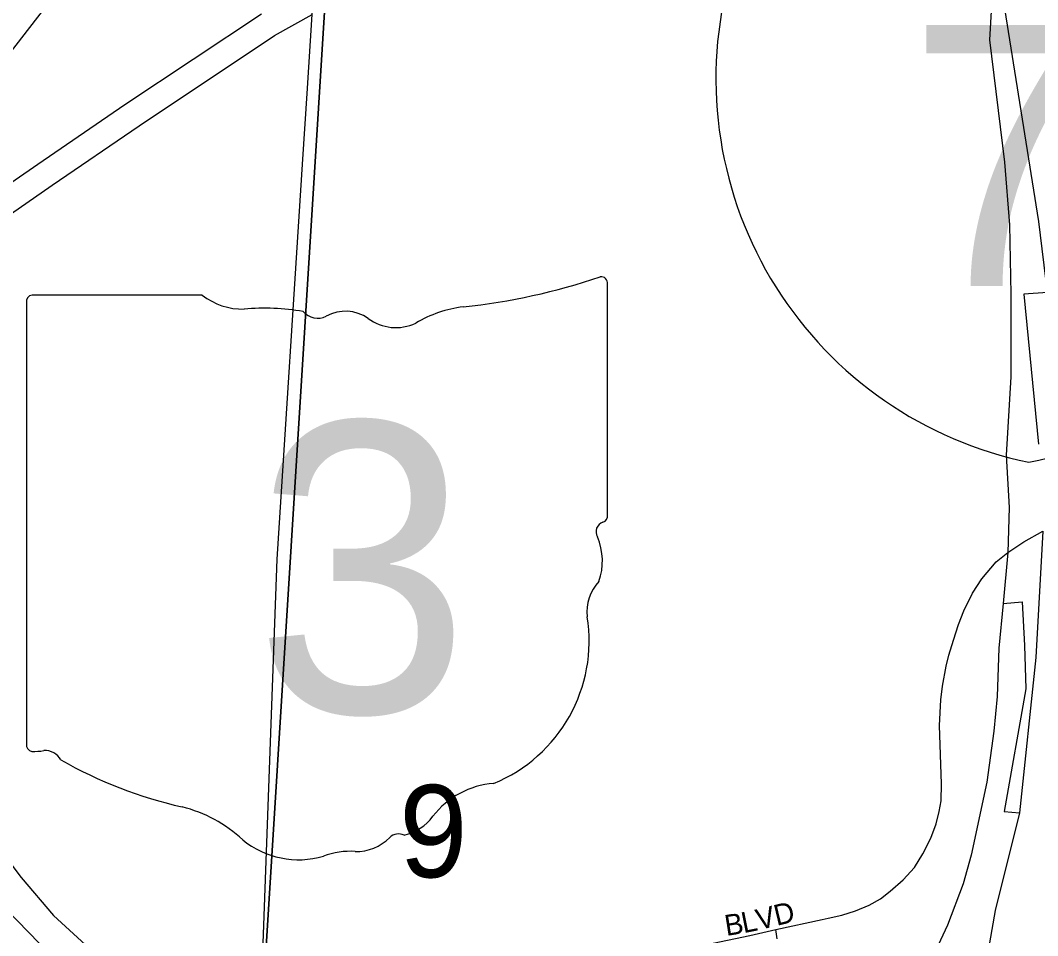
# Model space of a CAD drawing. Extents: x 0 to 34, y -6.2 to 22.
# Drawn here: x 7.114 to 7.5756, y 18.7615 to 19.1768 of the extents above; entities that cross this region are included whole.
import ezdxf

# ---------------------------------------------------------------- set-up
doc = ezdxf.new("R2010")
doc.units = 0
for name, color, linetype in [('GM_X_City_Street', 7, 'Continuous'), ('GM_X_City_Street_Text', 7, 'Continuous'), ('GM_X_Interchange_Ramps', 7, 'Continuous'), ('GM_X_Interstate_Route', 7, 'Continuous'), ('GM_X_Interstate_Shield', 7, 'Continuous'), ('GM_X_Rail_Line', 7, 'Continuous'), ('GM_X_Section', 7, 'Continuous'), ('GM_X_Section_Text', 7, 'Continuous'), ('GM_X_State_Route', 7, 'Continuous'), ('GM_X_State_Shield', 7, 'Continuous')]:
    doc.layers.add(name, color=color, linetype=linetype)

msp = doc.modelspace()

# ---------------------------------------------------------------- linework, layer by layer
at = {"layer": 'GM_X_City_Street'}
for points in [[(7.47785355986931, 18.768924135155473), (7.480502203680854, 18.76950733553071), (7.486678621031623, 18.77079357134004), (7.492855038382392, 18.77276952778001), (7.499118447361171, 18.775341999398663), (7.504263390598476, 18.778256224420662), (7.508724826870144, 18.781686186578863), (7.514559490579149, 18.786924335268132), (7.5196174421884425, 18.792498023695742), (7.523476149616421, 18.79858744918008), (7.527080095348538, 18.805708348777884), (7.5294847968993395, 18.81222651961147), (7.5308518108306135, 18.817800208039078), (7.531727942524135, 18.82268417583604), (7.531970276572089, 18.830407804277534), (7.530976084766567, 18.856840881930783), (7.5316720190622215, 18.868503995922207), (7.532454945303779, 18.874686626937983), (7.534107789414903, 18.883739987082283), (7.535325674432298, 18.888785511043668), (7.537332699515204, 18.895577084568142), (7.539594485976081, 18.90271041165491), (7.5421172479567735, 18.908893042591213), (7.546031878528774, 18.916896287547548), (7.550300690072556, 18.92342688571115), (7.556738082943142, 18.93108837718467), (7.5621129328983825, 18.935344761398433), (7.569271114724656, 18.940135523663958), (7.577976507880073, 18.94501327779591)], [(7.405165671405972, 18.753296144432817), (7.444990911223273, 18.76152894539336), (7.456741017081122, 18.764275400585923), (7.47785355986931, 18.768924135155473)]]:
    msp.add_lwpolyline(points, dxfattribs=at)
at = {"layer": 'GM_X_Interchange_Ramps'}
for points in [[(7.064625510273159, 19.057649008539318), (7.128440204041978, 19.10200239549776), (7.167841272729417, 19.12896985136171), (7.229319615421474, 19.16983735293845), (7.24638864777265, 19.17935052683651)], [(7.223354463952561, 19.179617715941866), (7.161441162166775, 19.138464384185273), (7.121959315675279, 19.111441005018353), (7.084565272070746, 19.08566657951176)], [(7.554656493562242, 19.183569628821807), (7.55371201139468, 19.167855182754), (7.560460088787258, 19.11239791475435), (7.562871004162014, 19.083951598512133), (7.563349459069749, 19.05260348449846), (7.563349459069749, 19.01499196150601), (7.561267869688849, 18.979480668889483), (7.562659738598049, 18.955806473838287), (7.5621129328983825, 18.935344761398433), (7.559876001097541, 18.912285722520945), (7.557900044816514, 18.89192964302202), (7.5571544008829, 18.870001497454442), (7.55574389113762, 18.854237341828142), (7.552581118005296, 18.831221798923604), (7.5453918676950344, 18.79801578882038), (7.541756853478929, 18.785091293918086), (7.534623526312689, 18.766363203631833), (7.527191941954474, 18.75037535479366)], [(7.5801015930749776, 19.053355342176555), (7.569233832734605, 19.05258484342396), (7.575913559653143, 18.98444541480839)], [(7.577976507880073, 18.94501327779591), (7.574720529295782, 18.887660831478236), (7.567338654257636, 18.817321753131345), (7.556284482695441, 18.772962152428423), (7.5495177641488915, 18.734020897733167), (7.5441615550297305, 18.70523282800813), (7.540445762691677, 18.679576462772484), (7.535021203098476, 18.647892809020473), (7.533722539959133, 18.6340051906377), (7.533710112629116, 18.633911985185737), (7.531150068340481, 18.60338407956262), (7.531901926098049, 18.564088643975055), (7.534635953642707, 18.536189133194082), (7.537854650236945, 18.516342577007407), (7.541477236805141, 18.493171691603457), (7.542440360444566, 18.48698284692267), (7.548859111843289, 18.445910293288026), (7.5626970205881, 18.376323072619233), (7.563622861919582, 18.36274613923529), (7.574701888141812, 18.29735937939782), (7.580884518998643, 18.260841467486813)], [(7.559876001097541, 18.912285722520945), (7.5685751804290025, 18.912981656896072), (7.569619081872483, 18.893135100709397), (7.570141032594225, 18.873468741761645), (7.56031096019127, 18.81781263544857), (7.567338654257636, 18.817321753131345)], [(7.0942772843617, 18.81399742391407), (7.083912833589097, 18.804937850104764), (7.0963899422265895, 18.787334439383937), (7.1079101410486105, 18.773260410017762), (7.127427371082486, 18.753096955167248), (7.145664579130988, 18.738059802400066), (7.163267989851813, 18.726222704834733), (7.18822842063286, 18.71245936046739), (7.211585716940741, 18.701579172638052), (7.218178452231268, 18.7003115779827)], [(7.457368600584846, 18.760118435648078), (7.456741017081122, 18.764275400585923)]]:
    msp.add_lwpolyline(points, dxfattribs=at)
at = {"layer": 'GM_X_Interstate_Route'}
for points in [[(7.562966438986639, 19.16785335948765), (7.560255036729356, 19.1849490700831), (7.559192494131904, 19.192386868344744), (7.558993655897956, 19.193778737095), (7.555079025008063, 19.22118115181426), (7.553538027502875, 19.23199298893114), (7.553314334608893, 19.23349049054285), (7.54600702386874, 19.28281483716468), (7.545876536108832, 19.283715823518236), (7.5297644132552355, 19.386384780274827), (7.520319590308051, 19.469163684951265), (7.506593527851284, 19.567538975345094), (7.500174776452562, 19.611935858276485), (7.497726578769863, 19.62890547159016), (7.486280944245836, 19.713560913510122), (7.479501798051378, 19.757671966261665), (7.477799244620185, 19.775064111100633), (7.475189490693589, 19.80612639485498), (7.4726977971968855, 19.838549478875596), (7.473561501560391, 19.871339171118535), (7.4761091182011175, 19.918420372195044), (7.480601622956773, 19.973647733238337)], [(7.5801015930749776, 19.053355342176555), (7.576037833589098, 19.085436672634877), (7.562966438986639, 19.16785335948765)], [(7.100520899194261, 18.805882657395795), (7.114347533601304, 18.78791231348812), (7.129024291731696, 18.770625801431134), (7.152692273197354, 18.749076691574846), (7.175179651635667, 18.734636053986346), (7.191689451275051, 18.72516637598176), (7.21898623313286, 18.71163915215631)]]:
    msp.add_lwpolyline(points, dxfattribs=at)
at = {"layer": 'GM_X_Interstate_Shield'}
for centre, radius, start, end in [((7.607133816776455, 19.150288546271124), 0.17755850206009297, 165.8066458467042, 258.4630388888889), ((7.536110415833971, 19.150288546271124), 0.1775585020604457, 281.53695833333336, 14.193353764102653)]:
    msp.add_arc(centre, radius, start, end, dxfattribs=at)
at = {"layer": 'GM_X_Rail_Line'}
msp.add_lwpolyline([(7.057229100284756, 19.055654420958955), (7.07835027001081, 19.1080690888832), (7.093116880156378, 19.138272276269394), (7.104646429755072, 19.156129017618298), (7.125523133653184, 19.182914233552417), (7.141344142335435, 19.199575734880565), (7.1584978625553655, 19.214339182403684), (7.171995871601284, 19.224743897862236), (7.18675931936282, 19.234304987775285), (7.201382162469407, 19.24274124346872), (7.219098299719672, 19.251318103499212), (7.238642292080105, 19.25933254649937), (7.255700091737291, 19.264476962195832)], dxfattribs=at)
at = {"layer": 'GM_X_Section'}
for points in [[(6.760777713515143, 19.269365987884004), (7.255460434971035, 19.23647296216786), (7.193512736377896, 18.242764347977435), (6.686302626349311, 18.2757952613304)], [(7.255460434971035, 19.23647296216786), (7.747779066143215, 19.203649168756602), (7.679756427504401, 18.21034633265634), (7.193512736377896, 18.242764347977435)]]:
    msp.add_lwpolyline(points, close=True, dxfattribs=at)
at = {"layer": 'GM_X_State_Route'}
for points in [[(7.244083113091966, 19.14359089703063), (7.24638864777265, 19.17935052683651), (7.247270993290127, 19.192946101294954), (7.2544229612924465, 19.264298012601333), (7.2541371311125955, 19.29170042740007), (7.2563529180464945, 19.312377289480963)], [(7.242160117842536, 19.11376458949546), (7.244083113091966, 19.14359089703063)], [(7.223745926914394, 18.745640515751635), (7.230462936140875, 18.932337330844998), (7.242160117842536, 19.11376458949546)]]:
    msp.add_lwpolyline(points, dxfattribs=at)
at = {"layer": 'GM_X_State_Shield'}
for p, q in [((7.380401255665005, 18.95242599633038), (7.380401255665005, 19.05711139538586)), ((7.196546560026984, 19.052152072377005), (7.119330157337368, 19.052152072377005)), ((7.116734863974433, 19.04870881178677), (7.116734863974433, 18.84858856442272)), ((7.380375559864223, 18.952451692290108), (7.380401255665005, 18.95242599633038))]:
    msp.add_line(p, q, dxfattribs=at)
for centre, radius, start, end in [((7.286479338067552, 19.324984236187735), 0.2796157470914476, 275.8444694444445, 288.9064527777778), ((7.3774767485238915, 19.057545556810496), 0.0029352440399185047, 351.8620861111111, 97.738), ((7.11975510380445, 19.0491349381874), 0.003054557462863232, 98.1301027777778, 188.13010277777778), ((7.214935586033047, 19.07538397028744), 0.02962754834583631, 231.61950555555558, 271.11188333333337), ((7.224758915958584, 18.939802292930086), 0.10636255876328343, 80.48669166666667, 94.98826944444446), ((7.322145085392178, 18.991029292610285), 0.056254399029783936, 97.34618055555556, 120.7688527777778), ((7.248905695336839, 19.050172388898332), 0.00854732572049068, 219.79206111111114, 297.1023694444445), ((7.261453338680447, 19.027042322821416), 0.017770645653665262, 54.466683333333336, 119.14113055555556), ((7.2843901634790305, 19.0587671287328), 0.021377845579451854, 233.85620555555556, 294.82819166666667), ((7.379723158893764, 18.94474077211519), 0.004542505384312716, 107.94398333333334, 210.33696666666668), ((7.377269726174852, 18.95202152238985), 0.003141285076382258, 289.6038111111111, 7.734130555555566), ((7.350824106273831, 18.931507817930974), 0.02726868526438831, 340.0329638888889, 23.649566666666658), ((7.390917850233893, 18.908616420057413), 0.019839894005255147, 136.80649722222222, 186.92959444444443), ((7.302142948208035, 18.895299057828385), 0.06993829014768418, 292.3088861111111, 8.985838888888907), ((7.119782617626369, 18.848150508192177), 0.0030816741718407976, 171.9583861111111, 258.30661388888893), ((7.120249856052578, 18.868624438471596), 0.023517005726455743, 267.33899444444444, 280.6038555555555), ((7.125061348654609, 18.8370431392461), 0.00847971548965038, 29.748380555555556, 93.27174722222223), ((7.232121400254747, 19.016842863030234), 0.20192143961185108, 240.41292222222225, 257.1985), ((7.3316321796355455, 18.79240524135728), 0.03830339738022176, 94.40312222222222, 142.57675), ((7.171921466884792, 18.758683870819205), 0.06317724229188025, 47.184155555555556, 75.83597222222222), ((7.283101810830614, 18.82919294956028), 0.022595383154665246, 282.8731916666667, 323.27711111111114), ((7.266343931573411, 18.821063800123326), 0.02135989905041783, 268.7770194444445, 315.54927222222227), ((7.285666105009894, 18.801682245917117), 0.006013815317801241, 65.75173055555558, 132.64842222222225), ((7.240251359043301, 18.836050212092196), 0.0400896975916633, 230.70037222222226, 286.29183611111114), ((7.263415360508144, 18.766860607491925), 0.03294109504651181, 85.69512222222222, 111.20994722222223)]:
    msp.add_arc(centre, radius, start, end, dxfattribs=at)

# ---------------------------------------------------------------- texts
at = {"layer": 'GM_X_City_Street_Text'}
for s, height, rotation, p in [('V', 0.00946969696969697, 13.395596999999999, (7.449035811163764, 18.763998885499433)), ('D', 0.00946969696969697, 13.503402, (7.457165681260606, 18.76593275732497)), ('B', 0.00946969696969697, 8.899403, (7.434305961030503, 18.761376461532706)), ('L', 0.009469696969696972, 11.301860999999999, (7.44213404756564, 18.762612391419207))]:
    msp.add_text(s, height=height, rotation=rotation, dxfattribs=at).set_placement(p)
at = {"layer": 'GM_X_Interstate_Shield'}
msp.add_text('71', height=0.11837121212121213, dxfattribs=at).set_placement((7.516937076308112, 19.056220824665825))
at = {"layer": 'GM_X_Section_Text'}
msp.add_text('9', height=0.041856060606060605, rotation=1e-05, dxfattribs=at).set_placement((7.2858197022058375, 18.788010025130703))
at = {"layer": 'GM_X_State_Shield'}
msp.add_text('3', height=0.13183620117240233, dxfattribs=at).set_placement((7.220126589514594, 18.862700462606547))

doc.saveas('drawing.dxf')
